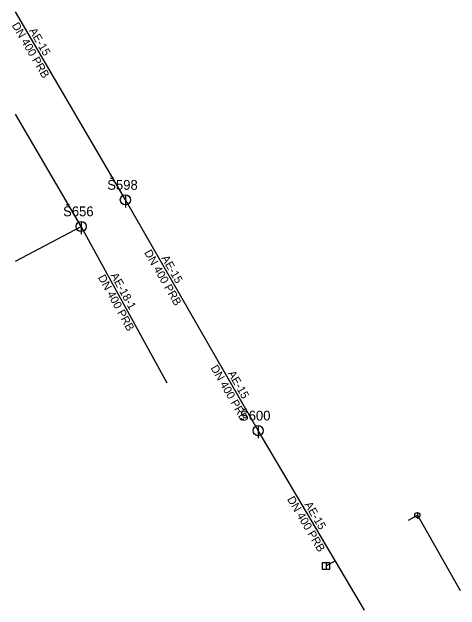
# Model space of a CAD drawing. Extents: x -483185 to -483096, y -1126492 to -1126374.
import ezdxf

# ---------------------------------------------------------------- set-up
doc = ezdxf.new("R2010")
doc.units = 0
for name, color, linetype in [('_pripojka_kanal_destova_priblizne_', 7, 'Continuous'), ('_pripojka_kanal_jednotna_priblizne_', 7, 'Continuous'), ('_stoka_jednotna_smvak_prevzato_z_dokumentace_', 7, 'Continuous'), ('Default', 7, 'Continuous'), ('MoLevel 119', 7, 'Continuous'), ('MoLevel 120', 7, 'Continuous'), ('MoLevel 57', 7, 'Continuous'), ('MoLevel 63', 7, 'Continuous'), ('MoLevel 68', 7, 'Continuous'), ('MoLevel 69', 7, 'Continuous')]:
    doc.layers.add(name, color=color, linetype=linetype)

# ---------------------------------------------------------------- blocks, each defined once
blk = doc.blocks.new('_vpust_')
at = {"layer": 'Default'}
blk.add_line((0, 0.000025), (0, -0.000025), dxfattribs=at)
blk.add_lwpolyline([(-0.000035, 0.000035), (0.000035, 0.000035), (0.000035, -0.000035), (-0.000035, -0.000035), (-0.000035, 0.000035)], dxfattribs=at)
blk = doc.blocks.new('_sachta_kanal_prip_')
at = {"layer": 'Default'}
blk.add_line((0, 0.00005), (0, -0.000075), dxfattribs=at)
blk.add_circle((0, 0), 0.00005, dxfattribs=at)
blk = doc.blocks.new('_sachta_kanal_prevzato_z_dokumentace_')
at = {"layer": 'Default'}
blk.add_line((0, 0.00005), (0, -0.000075), dxfattribs=at)
blk.add_circle((0, 0), 0.00005, dxfattribs=at)

msp = doc.modelspace()

# ---------------------------------------------------------------- linework, layer by layer
at = {"layer": '_pripojka_kanal_destova_priblizne_'}
msp.add_line((-483122.67, -1126482.92), (-483120.88, -1126481.91), dxfattribs=at)
at = {"layer": '_pripojka_kanal_jednotna_priblizne_'}
for p, q in [((-483106.43, -1126473.91), (-483104.69, -1126472.9)), ((-483104.69, -1126472.9), (-483096.28, -1126487.74))]:
    msp.add_line(p, q, dxfattribs=at)
at = {"layer": '_stoka_jednotna_smvak_prevzato_z_dokumentace_'}
for p, q in [((-483162.21, -1126410.84), (-483183.85, -1126373.82)), ((-483170.91, -1126416.06), (-483183.85, -1126393.98)), ((-483144.19, -1126442.14), (-483162.21, -1126410.84)), ((-483183.85, -1126422.91), (-483170.91, -1126416.06)), ((-483153.97, -1126446.9), (-483170.91, -1126416.06)), ((-483136.06, -1126456.28), (-483144.19, -1126442.14)), ((-483115.13, -1126491.61), (-483136.06, -1126456.28))]:
    msp.add_line(p, q, dxfattribs=at)

# ---------------------------------------------------------------- block references
at = {"layer": 'MoLevel 119', "xscale": 20000, "yscale": 20000}
for p in [(-483162.21, -1126410.84), (-483170.91, -1126416.06), (-483136.06, -1126456.28)]:
    msp.add_blockref('_sachta_kanal_prevzato_z_dokumentace_', p, dxfattribs=at)
at = {"layer": 'MoLevel 57', "xscale": 10000, "yscale": 10000}
msp.add_blockref('_sachta_kanal_prip_', (-483104.69, -1126472.9), dxfattribs=at)
at = {"layer": 'MoLevel 63', "xscale": 20000, "yscale": 20000}
msp.add_blockref('_vpust_', (-483122.67, -1126482.92), dxfattribs=at)

# ---------------------------------------------------------------- texts
at = {"layer": 'MoLevel 120'}
for s, p in [('Š598', (-483165.79, -1126408.84)), ('Š656', (-483174.49, -1126414.06)), ('Š600', (-483139.64, -1126454.28))]:
    msp.add_text(s, height=1.926, dxfattribs=at).set_placement(p)
at = {"layer": 'MoLevel 68'}
for rotation, p in [(300.3132, (-483184.65, -1126376.44)), (299.919, (-483158.56, -1126421.2)), (298.7794, (-483167.67, -1126426.09)), (299.9214, (-483145.48, -1126443.92)), (300.6422, (-483130.4, -1126469.78))]:
    msp.add_text('DN 400 PRB', height=1.605, rotation=rotation, dxfattribs=at).set_placement(p)
at = {"layer": 'MoLevel 69'}
for s, rotation, p in [('AE-15', 300.3132, (-483181.24, -1126377.5)), ('AE-15', 299.919, (-483155.17, -1126422.28)), ('AE-18-1', 298.7794, (-483165.18, -1126425.69)), ('AE-15', 299.9214, (-483142.09, -1126445)), ('AE-15', 300.6422, (-483126.98, -1126470.82))]:
    msp.add_text(s, height=1.605, rotation=rotation, dxfattribs=at).set_placement(p)

doc.saveas('drawing.dxf')
